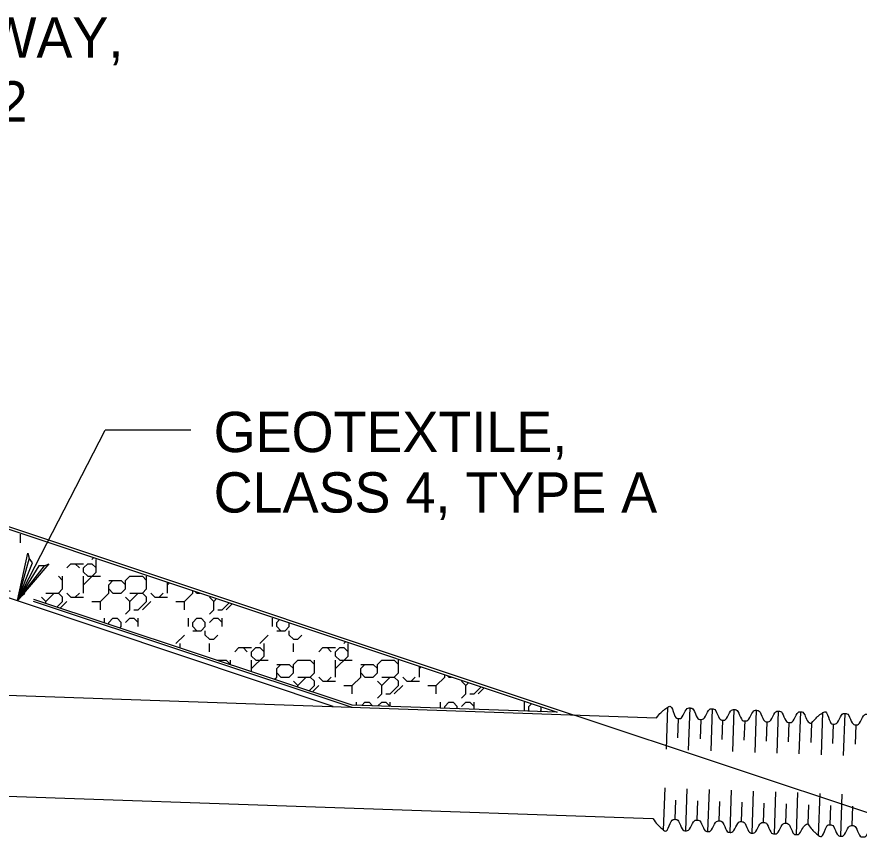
# Model space of a CAD drawing. Extents: x 636462 to 639890, y 299944 to 300538.
# Drawn here: x 638545.1 to 638607.7, y 300117.8 to 300179.1 of the extents above; entities that cross this region are included whole.
import ezdxf

# ---------------------------------------------------------------- set-up
doc = ezdxf.new("R2010")
doc.units = 0
doc.layers.add('Default', color=7, linetype='Continuous')

msp = doc.modelspace()

# ---------------------------------------------------------------- linework, layer by layer
at = {"layer": 'Default'}
for p, q in [((638465.993, 300167.339), (638586.564, 300127.149)), ((638545.147, 300135.661), (638551.669, 300148.347)), ((638558.059, 300148.347), (638551.669, 300148.347)), ((638545.384, 300139.969), (638545.384, 300140.594)), ((638548.82, 300138.096), (638549.132, 300138.408)), ((638549.132, 300138.408), (638550.069, 300138.408)), ((638549.756, 300138.096), (638549.444, 300138.408)), ((638550.069, 300138.096), (638550.381, 300138.408)), ((638550.381, 300138.408), (638550.693, 300138.408)), ((638550.693, 300138.72), (638550.831, 300138.858)), ((638551.006, 300138.096), (638550.693, 300138.408)), ((638551.006, 300137.783), (638551.006, 300138.72)), ((638550.069, 300137.783), (638550.069, 300138.096)), ((638550.381, 300137.471), (638550.069, 300137.783)), ((638550.069, 300136.846), (638551.006, 300137.783)), ((638548.507, 300137.159), (638548.195, 300137.471)), ((638548.507, 300136.534), (638548.507, 300137.471)), ((638550.069, 300136.222), (638550.069, 300137.471)), ((638550.381, 300137.471), (638551.318, 300137.471)), ((638551.943, 300136.846), (638552.255, 300137.159)), ((638551.943, 300137.159), (638552.879, 300137.159)), ((638553.192, 300136.846), (638552.879, 300137.159)), ((638553.192, 300137.159), (638553.504, 300137.471)), ((638553.192, 300136.534), (638553.192, 300137.159)), ((638553.504, 300137.471), (638554.441, 300137.471)), ((638554.753, 300137.159), (638554.441, 300137.471)), ((638554.753, 300136.534), (638554.753, 300137.471)), ((638556.315, 300136.222), (638556.315, 300137.027)), ((638548.195, 300136.222), (638548.507, 300136.534)), ((638551.943, 300136.222), (638551.943, 300136.846)), ((638552.255, 300136.222), (638551.943, 300136.534)), ((638552.879, 300136.222), (638553.192, 300136.534)), ((638554.441, 300136.222), (638554.753, 300136.534)), ((638556.315, 300136.846), (638556.45, 300136.982)), ((638558.188, 300136.222), (638558.188, 300136.401)), ((638545.512, 300136.037), (638545.697, 300136.222)), ((638547.258, 300135.597), (638546.946, 300135.909)), ((638547.258, 300135.597), (638547.883, 300136.222)), ((638547.258, 300136.222), (638548.195, 300136.222)), ((638548.507, 300135.909), (638548.195, 300136.222)), ((638548.507, 300135.597), (638548.507, 300135.909)), ((638549.132, 300135.909), (638548.82, 300136.222)), ((638549.132, 300135.909), (638550.069, 300135.909)), ((638549.444, 300135.909), (638549.756, 300136.222)), ((638551.318, 300135.597), (638551.943, 300136.222)), ((638552.255, 300136.222), (638552.879, 300136.222)), ((638553.504, 300135.597), (638553.192, 300135.909)), ((638553.504, 300135.597), (638554.129, 300136.222)), ((638553.504, 300136.222), (638554.441, 300136.222)), ((638554.753, 300135.909), (638554.441, 300136.222)), ((638554.753, 300135.597), (638554.753, 300135.909)), ((638555.378, 300135.909), (638555.065, 300136.222)), ((638555.378, 300135.909), (638556.315, 300135.909)), ((638555.69, 300135.909), (638556.002, 300136.222)), ((638557.564, 300135.597), (638558.188, 300136.222)), ((638558.501, 300136.222), (638558.388, 300136.334)), ((638558.501, 300136.222), (638558.725, 300136.222)), ((638559.75, 300135.597), (638559.438, 300135.909)), ((638559.75, 300135.597), (638559.962, 300135.809)), ((638547.258, 300135.458), (638547.258, 300135.597)), ((638548.091, 300135.181), (638548.507, 300135.597)), ((638548.326, 300135.103), (638548.82, 300135.597)), ((638550.693, 300135.597), (638551.318, 300135.597)), ((638551.318, 300134.973), (638551.318, 300135.597)), ((638553.504, 300134.973), (638553.504, 300135.597)), ((638554.129, 300134.973), (638554.753, 300135.597)), ((638554.441, 300134.973), (638555.065, 300135.597)), ((638556.939, 300135.597), (638557.564, 300135.597)), ((638557.564, 300134.973), (638557.564, 300135.597)), ((638559.75, 300134.973), (638559.75, 300135.597)), ((638560.375, 300134.973), (638560.898, 300135.496)), ((638560.687, 300134.973), (638561.132, 300135.418)), ((638553.192, 300134.66), (638553.504, 300134.973)), ((638553.816, 300134.973), (638554.129, 300134.973)), ((638559.438, 300134.66), (638559.75, 300134.973)), ((638560.062, 300134.973), (638560.375, 300134.973)), ((638551.63, 300134.007), (638551.63, 300134.348)), ((638551.943, 300134.036), (638552.255, 300134.348)), ((638551.943, 300133.903), (638551.943, 300134.036)), ((638552.255, 300134.348), (638552.567, 300134.348)), ((638552.879, 300134.036), (638552.567, 300134.348)), ((638552.879, 300133.723), (638552.879, 300134.036)), ((638553.192, 300134.036), (638553.504, 300134.348)), ((638553.504, 300134.348), (638553.816, 300134.348)), ((638554.129, 300134.036), (638553.816, 300134.348)), ((638554.129, 300133.723), (638554.129, 300134.348)), ((638557.876, 300133.723), (638557.876, 300134.348)), ((638558.188, 300134.036), (638558.501, 300134.348)), ((638558.188, 300133.723), (638558.188, 300134.036)), ((638558.501, 300134.348), (638558.813, 300134.348)), ((638559.125, 300134.036), (638558.813, 300134.348)), ((638559.125, 300133.723), (638559.125, 300134.036)), ((638559.438, 300134.036), (638559.75, 300134.348)), ((638559.75, 300134.348), (638560.062, 300134.348)), ((638560.375, 300134.036), (638560.062, 300134.348)), ((638560.375, 300133.723), (638560.375, 300134.348)), ((638564.122, 300133.723), (638564.122, 300134.348)), ((638564.434, 300134.036), (638564.644, 300134.245)), ((638564.434, 300133.723), (638564.434, 300134.036)), ((638565.371, 300133.723), (638565.371, 300134.002)), ((638552.781, 300133.625), (638552.879, 300133.723)), ((638558.501, 300133.411), (638558.188, 300133.723)), ((638558.188, 300133.411), (638558.813, 300133.411)), ((638558.813, 300133.411), (638559.125, 300133.723)), ((638559.125, 300133.099), (638559.125, 300133.411)), ((638564.747, 300133.411), (638564.434, 300133.723)), ((638564.434, 300133.411), (638565.059, 300133.411)), ((638565.059, 300133.411), (638565.371, 300133.723)), ((638565.371, 300133.099), (638565.371, 300133.411)), ((638556.939, 300132.474), (638557.564, 300133.099)), ((638559.438, 300132.786), (638559.125, 300133.099)), ((638559.438, 300132.786), (638559.75, 300132.786)), ((638559.75, 300132.786), (638560.062, 300133.099)), ((638563.185, 300132.474), (638563.81, 300133.099)), ((638565.684, 300132.786), (638565.371, 300133.099)), ((638565.684, 300132.786), (638565.996, 300132.786)), ((638565.996, 300132.786), (638566.308, 300133.099)), ((638557.252, 300132.141), (638557.252, 300132.474)), ((638559.438, 300131.85), (638559.438, 300132.474)), ((638561.311, 300131.85), (638561.624, 300132.162)), ((638561.624, 300132.162), (638562.561, 300132.162)), ((638562.248, 300131.85), (638561.936, 300132.162)), ((638562.561, 300131.85), (638562.873, 300132.162)), ((638562.873, 300132.162), (638563.185, 300132.162)), ((638563.497, 300131.85), (638563.185, 300132.162)), ((638563.497, 300131.537), (638563.497, 300132.474)), ((638565.684, 300131.85), (638565.684, 300132.474)), ((638567.557, 300131.85), (638567.87, 300132.162)), ((638567.87, 300132.162), (638568.807, 300132.162)), ((638568.494, 300131.85), (638568.182, 300132.162)), ((638568.807, 300131.85), (638569.119, 300132.162)), ((638569.119, 300132.162), (638569.431, 300132.162)), ((638569.431, 300132.474), (638569.56, 300132.603)), ((638569.743, 300131.85), (638569.431, 300132.162)), ((638569.743, 300131.537), (638569.743, 300132.474)), ((638562.561, 300131.537), (638562.561, 300131.85)), ((638562.873, 300131.225), (638562.561, 300131.537)), ((638562.561, 300130.6), (638563.497, 300131.537)), ((638568.807, 300131.537), (638568.807, 300131.85)), ((638569.119, 300131.225), (638568.807, 300131.537)), ((638568.807, 300130.6), (638569.743, 300131.537)), ((638480.847, 300130.841), (638592.667, 300126.936)), ((638560.011, 300131.225), (638560.687, 300131.225)), ((638560.999, 300130.913), (638560.687, 300131.225)), ((638560.999, 300130.897), (638560.999, 300131.225)), ((638562.561, 300130.379), (638562.561, 300131.225)), ((638562.873, 300131.225), (638563.81, 300131.225)), ((638564.434, 300130.6), (638564.747, 300130.913)), ((638564.434, 300130.913), (638565.371, 300130.913)), ((638565.684, 300130.6), (638565.371, 300130.913)), ((638565.684, 300130.913), (638565.996, 300131.225)), ((638565.684, 300130.288), (638565.684, 300130.913)), ((638565.996, 300131.225), (638566.933, 300131.225)), ((638567.245, 300130.913), (638566.933, 300131.225)), ((638567.245, 300130.288), (638567.245, 300131.225)), ((638568.807, 300129.976), (638568.807, 300131.225)), ((638569.119, 300131.225), (638570.056, 300131.225)), ((638570.68, 300130.6), (638570.993, 300130.913)), ((638570.68, 300130.913), (638571.617, 300130.913)), ((638571.929, 300130.6), (638571.617, 300130.913)), ((638571.929, 300130.913), (638572.242, 300131.225)), ((638571.929, 300130.288), (638571.929, 300130.913)), ((638572.242, 300131.225), (638573.179, 300131.225)), ((638573.491, 300130.913), (638573.179, 300131.225)), ((638573.491, 300130.288), (638573.491, 300131.225)), ((638575.052, 300129.976), (638575.052, 300130.769)), ((638564.434, 300129.976), (638564.434, 300130.6)), ((638564.747, 300129.976), (638564.434, 300130.288)), ((638565.371, 300129.976), (638565.684, 300130.288)), ((638566.933, 300129.976), (638567.245, 300130.288)), ((638570.68, 300129.976), (638570.68, 300130.6)), ((638570.993, 300129.976), (638570.68, 300130.288)), ((638571.617, 300129.976), (638571.929, 300130.288)), ((638573.179, 300129.976), (638573.491, 300130.288)), ((638575.052, 300130.6), (638575.179, 300130.727)), ((638576.926, 300129.976), (638576.926, 300130.144)), ((638564.27, 300129.811), (638564.434, 300129.976)), ((638564.747, 300129.976), (638565.371, 300129.976)), ((638565.996, 300129.351), (638565.684, 300129.664)), ((638565.996, 300129.351), (638566.62, 300129.976)), ((638565.996, 300129.976), (638566.933, 300129.976)), ((638567.245, 300129.664), (638566.933, 300129.976)), ((638567.245, 300129.351), (638567.245, 300129.664)), ((638567.87, 300129.664), (638567.557, 300129.976)), ((638567.87, 300129.664), (638568.807, 300129.664)), ((638568.182, 300129.664), (638568.494, 300129.976)), ((638570.056, 300129.351), (638570.68, 300129.976)), ((638570.993, 300129.976), (638571.617, 300129.976)), ((638572.242, 300129.351), (638571.929, 300129.664)), ((638572.242, 300129.351), (638572.866, 300129.976)), ((638572.242, 300129.976), (638573.179, 300129.976)), ((638573.491, 300129.664), (638573.179, 300129.976)), ((638573.491, 300129.351), (638573.491, 300129.664)), ((638574.116, 300129.664), (638573.803, 300129.976)), ((638574.116, 300129.664), (638575.052, 300129.664)), ((638574.428, 300129.664), (638574.74, 300129.976)), ((638576.302, 300129.351), (638576.926, 300129.976)), ((638577.239, 300129.976), (638577.143, 300130.071)), ((638577.239, 300129.976), (638577.429, 300129.976)), ((638578.488, 300129.351), (638578.175, 300129.664)), ((638578.488, 300129.351), (638578.691, 300129.554)), ((638565.996, 300129.238), (638565.996, 300129.351)), ((638566.849, 300128.955), (638567.245, 300129.351)), ((638567.083, 300128.877), (638567.557, 300129.351)), ((638569.431, 300129.351), (638570.056, 300129.351)), ((638570.056, 300128.727), (638570.056, 300129.351)), ((638572.242, 300128.727), (638572.242, 300129.351)), ((638572.866, 300128.727), (638573.491, 300129.351)), ((638573.179, 300128.727), (638573.803, 300129.351)), ((638575.677, 300129.351), (638576.302, 300129.351)), ((638576.302, 300128.727), (638576.302, 300129.351)), ((638578.488, 300128.727), (638578.488, 300129.351)), ((638579.112, 300128.727), (638579.627, 300129.242)), ((638579.425, 300128.727), (638579.861, 300129.163)), ((638571.929, 300128.414), (638572.242, 300128.727)), ((638572.554, 300128.727), (638572.866, 300128.727)), ((638578.175, 300128.414), (638578.488, 300128.727)), ((638578.8, 300128.727), (638579.112, 300128.727)), ((638570.368, 300127.881), (638570.368, 300128.102)), ((638570.758, 300127.867), (638570.993, 300128.102)), ((638570.993, 300128.102), (638571.305, 300128.102)), ((638571.568, 300127.839), (638571.305, 300128.102)), ((638571.964, 300127.825), (638572.242, 300128.102)), ((638572.242, 300128.102), (638572.554, 300128.102)), ((638572.863, 300127.793), (638572.554, 300128.102)), ((638572.866, 300127.793), (638572.866, 300128.102)), ((638576.614, 300127.66), (638576.614, 300128.102)), ((638576.926, 300127.79), (638577.239, 300128.102)), ((638576.926, 300127.649), (638576.926, 300127.79)), ((638577.239, 300128.102), (638577.551, 300128.102)), ((638577.863, 300127.79), (638577.551, 300128.102)), ((638577.863, 300127.615), (638577.863, 300127.79)), ((638578.175, 300127.79), (638578.488, 300128.102)), ((638578.488, 300128.102), (638578.8, 300128.102)), ((638579.112, 300127.79), (638578.8, 300128.102)), ((638579.112, 300127.571), (638579.112, 300128.102)), ((638582.86, 300127.477), (638582.86, 300128.102)), ((638583.172, 300127.79), (638583.373, 300127.991)), ((638583.172, 300127.477), (638583.172, 300127.79)), ((638584.109, 300127.477), (638584.109, 300127.745)), ((638593.41, 300124.599), (638593.52, 300127.731)), ((638595.058, 300124.542), (638595.168, 300127.673)), ((638596.813, 300127.616), (638596.704, 300124.484)), ((638583.224, 300127.425), (638583.172, 300127.477)), ((638584.028, 300127.397), (638584.109, 300127.477)), ((638611.696, 300118.772), (638586.564, 300127.149)), ((638598.352, 300124.427), (638598.461, 300127.558)), ((638600, 300124.369), (638600.109, 300127.501)), ((638601.648, 300124.312), (638601.757, 300127.443)), ((638603.296, 300124.254), (638603.405, 300127.386)), ((638604.944, 300124.197), (638605.053, 300127.328)), ((638606.592, 300124.139), (638606.701, 300127.271)), ((638594.265, 300125.443), (638594.315, 300126.878)), ((638595.961, 300126.821), (638595.911, 300125.385)), ((638597.559, 300125.327), (638597.609, 300126.763)), ((638599.206, 300125.27), (638599.257, 300126.706)), ((638600.854, 300125.212), (638600.905, 300126.648)), ((638602.502, 300125.155), (638602.552, 300126.591)), ((638604.2, 300126.533), (638604.15, 300125.097)), ((638605.798, 300125.038), (638605.848, 300126.475)), ((638607.496, 300126.418), (638607.446, 300124.98)), ((638480.586, 300123.35), (638592.405, 300119.445)), ((638593.201, 300118.592), (638593.31, 300121.724)), ((638594.849, 300118.535), (638594.958, 300121.666)), ((638596.494, 300118.477), (638596.604, 300121.609)), ((638598.142, 300118.42), (638598.252, 300121.551)), ((638599.79, 300118.362), (638599.9, 300121.494)), ((638601.438, 300118.305), (638601.547, 300121.436)), ((638603.086, 300118.247), (638603.195, 300121.379)), ((638594.053, 300119.388), (638594.104, 300120.825)), ((638595.699, 300119.33), (638595.749, 300120.768)), ((638597.347, 300119.273), (638597.397, 300120.71)), ((638604.734, 300118.19), (638604.843, 300121.321)), ((638606.382, 300118.132), (638606.491, 300121.264)), ((638598.995, 300119.215), (638599.045, 300120.653)), ((638600.643, 300119.158), (638600.693, 300120.595)), ((638602.291, 300119.1), (638602.341, 300120.538)), ((638603.989, 300120.478), (638603.939, 300119.042)), ((638605.587, 300118.985), (638605.637, 300120.421)), ((638607.235, 300118.927), (638607.285, 300120.363))]:
    msp.add_line(p, q, dxfattribs=at)
for points in [[(638419.787, 300159.33), (638427.928, 300154.599), (638488.624, 300154.599), (638568.6, 300127.803)], [(638544.627, 300136.331), (638488.696, 300154.897), (638428.027, 300154.915), (638420.199, 300159.477), (638489.373, 300159.381), (638585.285, 300127.352), (638570.051, 300127.892), (638546.379, 300135.75)], [(638547.176, 300138.256), (638547.497, 300138.395), (638545.147, 300135.661), (638547.176, 300138.256), (638546.755, 300138.249), (638545.147, 300135.661), (638546.285, 300138.48), (638546.033, 300138.813), (638545.147, 300135.661), (638545.934, 300139.179), (638546.033, 300138.813)], [(638546.328, 300135.623), (638570.017, 300127.727)]]:
    msp.add_lwpolyline(points, dxfattribs=at)
for points in [[(638592.667, 300126.936), (638592.954, 300127.293), (638593.238, 300127.546), (638593.52, 300127.731), (638593.801, 300127.916), (638594.04, 300126.888), (638594.315, 300126.878), (638594.59, 300126.869), (638594.893, 300127.683), (638595.168, 300127.673), (638595.442, 300127.664), (638595.686, 300126.83), (638595.961, 300126.821), (638596.235, 300126.811), (638596.539, 300127.626), (638596.813, 300127.616), (638597.088, 300127.606), (638597.334, 300126.773), (638597.609, 300126.763), (638597.883, 300126.754), (638598.187, 300127.568), (638598.461, 300127.558), (638598.736, 300127.549), (638598.982, 300126.715), (638599.257, 300126.706), (638599.531, 300126.696), (638599.835, 300127.51), (638600.109, 300127.501), (638600.384, 300127.491), (638600.63, 300126.658), (638600.905, 300126.648), (638601.179, 300126.639), (638601.483, 300127.453), (638601.757, 300127.443), (638602.032, 300127.434), (638602.278, 300126.6), (638602.552, 300126.591), (638602.827, 300126.581), (638603.131, 300127.395), (638603.405, 300127.386), (638603.68, 300127.376), (638603.924, 300126.491), (638604.2, 300126.533)], [(638604.2, 300126.533), (638604.488, 300126.89), (638604.772, 300127.143), (638605.053, 300127.328), (638605.335, 300127.513), (638605.574, 300126.485), (638605.848, 300126.475), (638606.123, 300126.466), (638606.426, 300127.28), (638606.701, 300127.271), (638606.976, 300127.261), (638607.222, 300126.428), (638607.496, 300126.418), (638607.771, 300126.408), (638608.074, 300127.223), (638608.349, 300127.213), (638608.624, 300127.204), (638608.869, 300126.37), (638609.144, 300126.36), (638609.419, 300126.351), (638609.722, 300127.165), (638609.997, 300127.156), (638610.272, 300127.146), (638610.517, 300126.312), (638610.792, 300126.303), (638611.067, 300126.293), (638611.37, 300127.108), (638611.645, 300127.098), (638611.919, 300127.088), (638612.165, 300126.255), (638612.44, 300126.245), (638612.715, 300126.236), (638613.018, 300127.05), (638613.293, 300127.04), (638613.567, 300127.031), (638613.813, 300126.197), (638614.088, 300126.188), (638614.363, 300126.178), (638614.666, 300126.993), (638614.941, 300126.983), (638615.215, 300126.973), (638615.459, 300126.088), (638615.736, 300126.13)], [(638592.405, 300119.445), (638592.667, 300119.069), (638592.933, 300118.797), (638593.201, 300118.592), (638593.468, 300118.388), (638593.779, 300119.397), (638594.053, 300119.388), (638594.328, 300119.378), (638594.574, 300118.544), (638594.849, 300118.535), (638595.123, 300118.525), (638595.425, 300119.34), (638595.699, 300119.33), (638595.974, 300119.321), (638596.22, 300118.487), (638596.494, 300118.477), (638596.769, 300118.468), (638597.072, 300119.282), (638597.347, 300119.273), (638597.622, 300119.263), (638597.868, 300118.429), (638598.142, 300118.42), (638598.417, 300118.41), (638598.72, 300119.225), (638598.995, 300119.215), (638599.27, 300119.206), (638599.516, 300118.372), (638599.79, 300118.362), (638600.065, 300118.353), (638600.368, 300119.167), (638600.643, 300119.158), (638600.918, 300119.148), (638601.163, 300118.314), (638601.438, 300118.305), (638601.713, 300118.295), (638602.016, 300119.11), (638602.291, 300119.1), (638602.566, 300119.09), (638602.811, 300118.257), (638603.086, 300118.247), (638603.361, 300118.238), (638603.664, 300119.052), (638603.939, 300119.042)], [(638603.939, 300119.042), (638604.201, 300118.666), (638604.466, 300118.394), (638604.734, 300118.19), (638605.002, 300117.986), (638605.312, 300118.994), (638605.587, 300118.985), (638605.861, 300118.975), (638606.107, 300118.142), (638606.382, 300118.132), (638606.657, 300118.123), (638606.96, 300118.937), (638607.235, 300118.927), (638607.509, 300118.918), (638607.755, 300118.084), (638608.03, 300118.075), (638608.304, 300118.065), (638608.608, 300118.879), (638608.883, 300118.87), (638609.157, 300118.86), (638609.403, 300118.027), (638609.678, 300118.017), (638609.952, 300118.007), (638610.256, 300118.822), (638610.53, 300118.812), (638610.805, 300118.803), (638611.051, 300117.969), (638611.326, 300117.96), (638611.6, 300117.95), (638611.904, 300118.764), (638612.178, 300118.755), (638612.453, 300118.745), (638612.699, 300117.912), (638612.974, 300117.902), (638613.248, 300117.892), (638613.552, 300118.707), (638613.826, 300118.697), (638614.101, 300118.688), (638614.347, 300117.854), (638614.621, 300117.844), (638614.896, 300117.835), (638615.2, 300118.649), (638615.474, 300118.64)]]:
    msp.add_open_spline(points, degree=3, dxfattribs=at)

# ---------------------------------------------------------------- texts
for s, p in [('EMERGENCY SPILLWAY,', (638504.908, 300176.049)), ('SEE DETAIL SHEET 2', (638504.908, 300171.302)), ('GEOTEXTILE,', (638559.747, 300146.707)), ('CLASS 4, TYPE A', (638559.747, 300142.21))]:
    msp.add_text(s, height=2.99804, dxfattribs=at).set_placement(p)

doc.saveas('drawing.dxf')
